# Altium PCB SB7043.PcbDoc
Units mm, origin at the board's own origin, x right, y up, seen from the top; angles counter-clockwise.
Board outline 70 x 43 mm, 2 copper layers (Top Layer, Bottom Layer); 0 components, 0 nets, 4 pads, 0 vias.
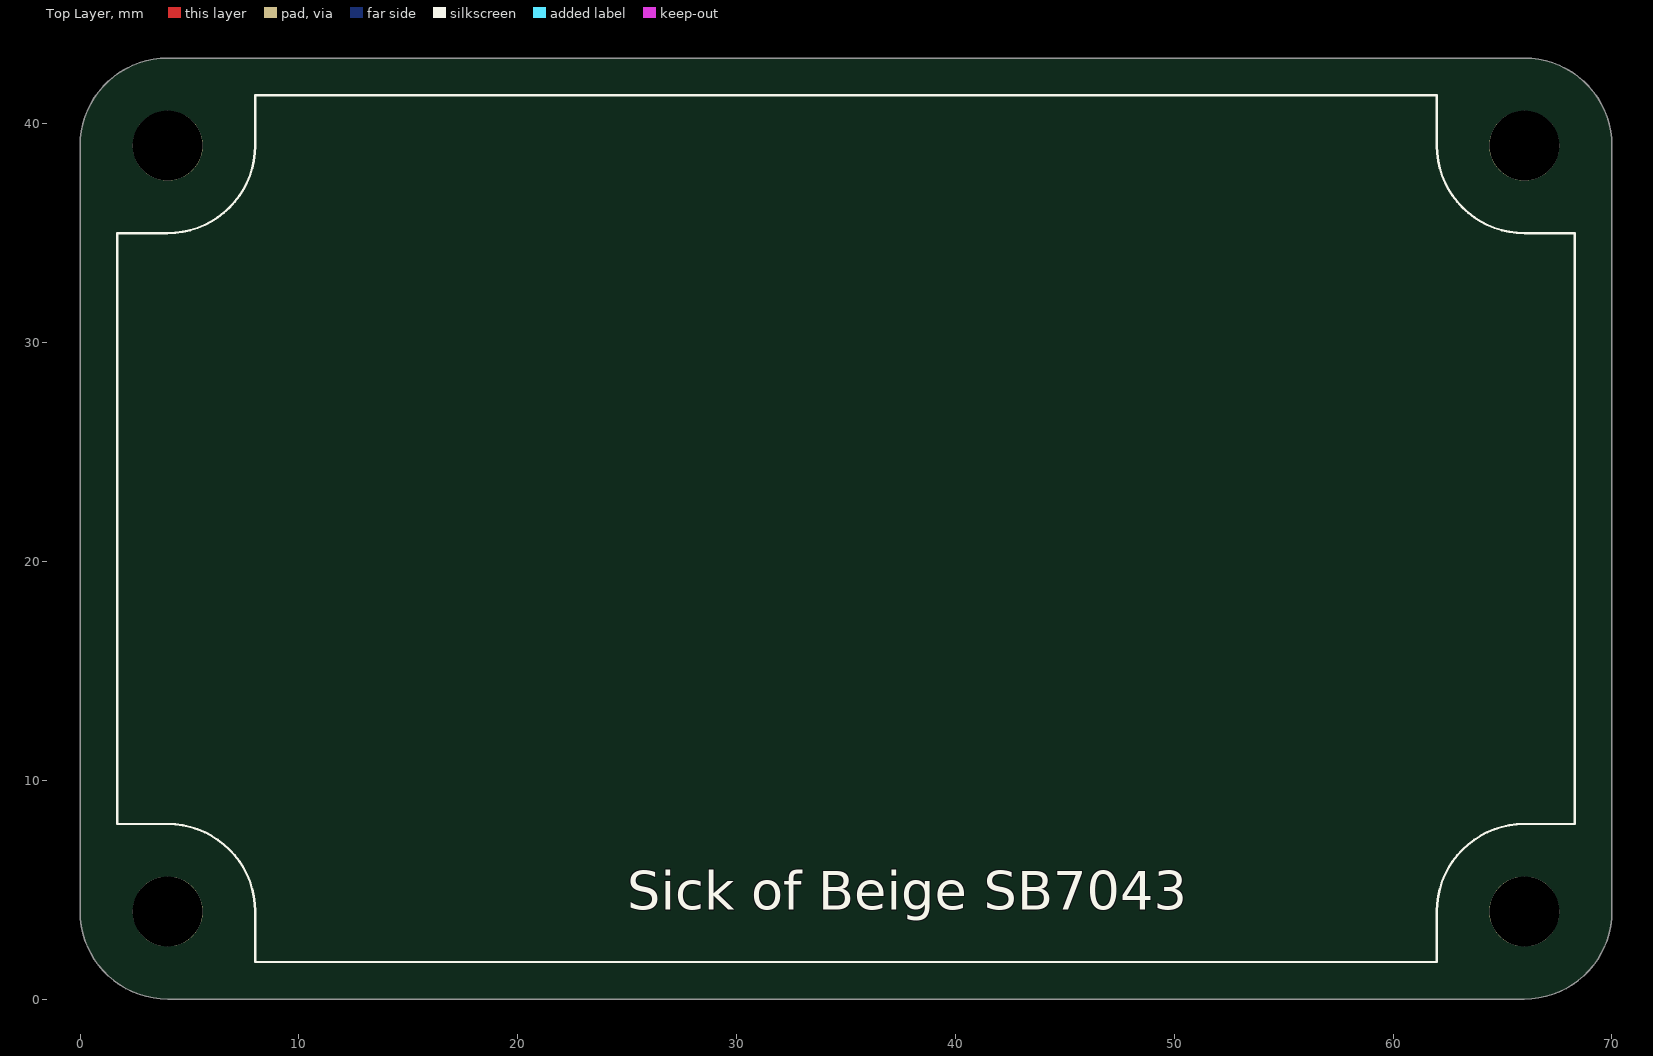
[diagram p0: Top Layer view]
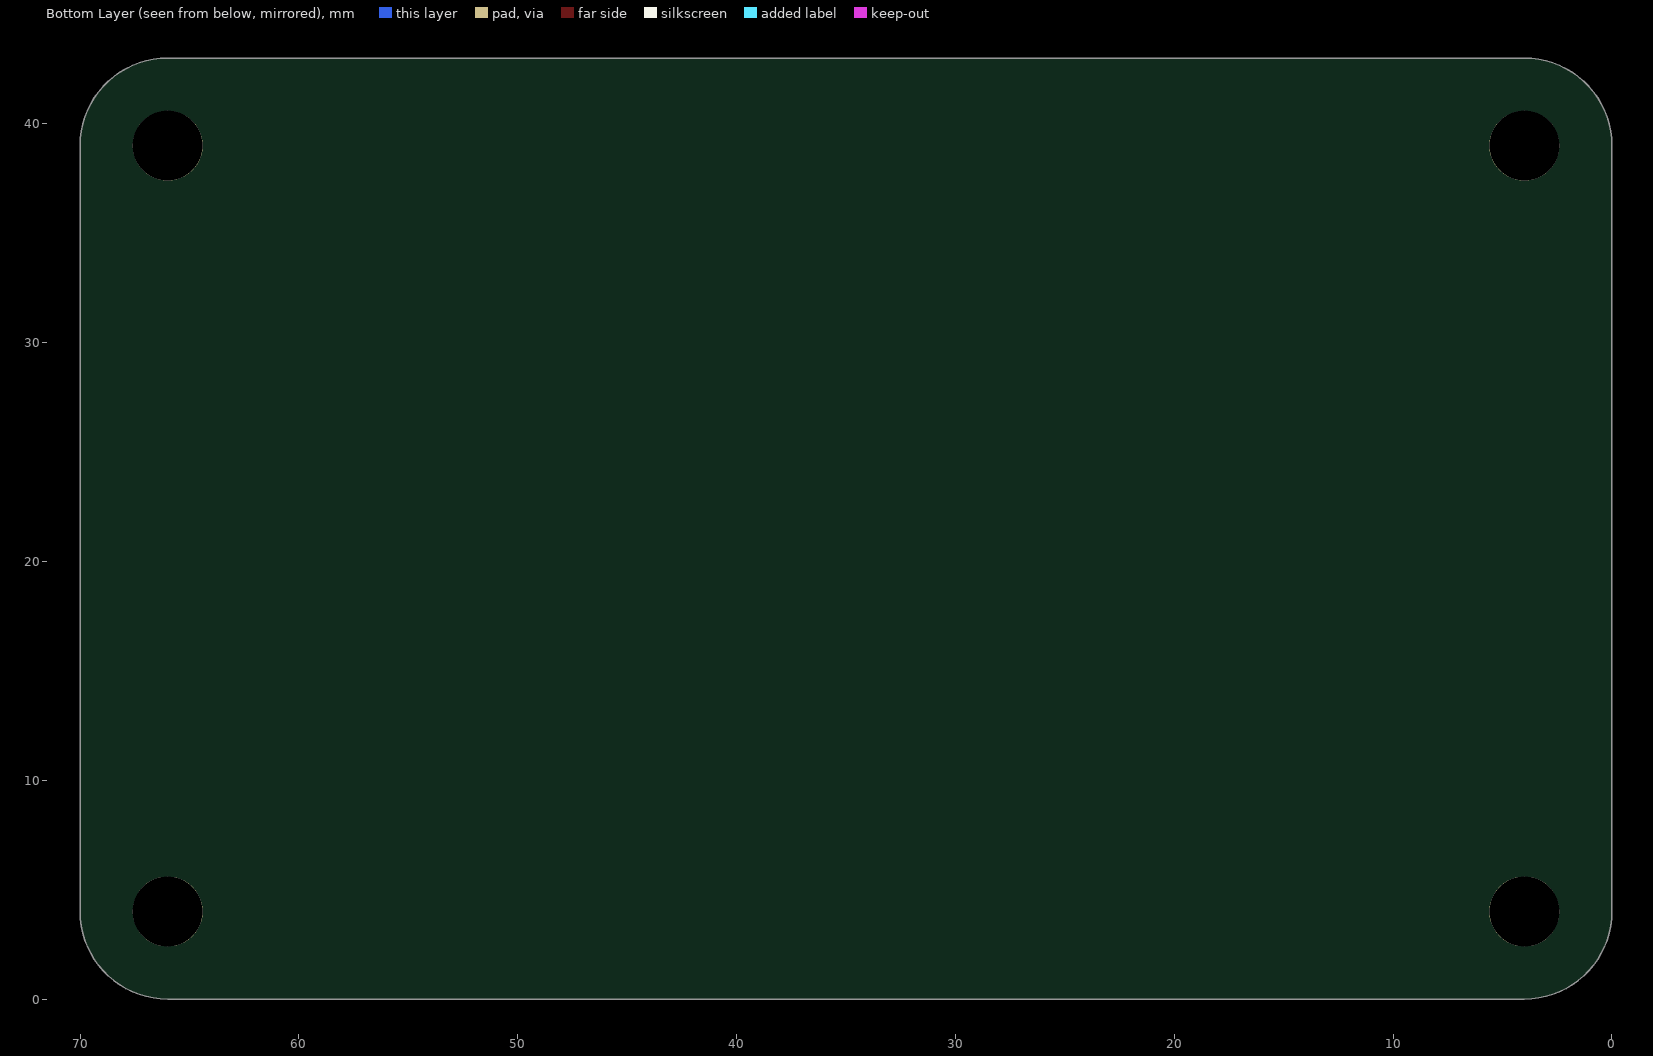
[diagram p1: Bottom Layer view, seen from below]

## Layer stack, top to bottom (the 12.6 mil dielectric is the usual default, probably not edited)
Top Layer: signal copper 0.0356
Dielectric: dielectric 0.32, FR-4, Dk 4.8
Bottom Layer: signal copper 0.0356

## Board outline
4,0 cw(c4,4) 0,4 0,39 cw(c4,39) 4,43 66,43 cw(c66,39) 70,39 70,4 cw(c66,4) 66,0

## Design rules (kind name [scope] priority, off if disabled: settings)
Clearance [All] p1: gap=0.254
PolygonConnect [All] p1: connectstyle=Relief reliefconductorwidth=0.254 reliefentries=4 polygonreliefangle="90 Angle" airgapwidth=0.254
RoutingVias [All] p1: holewidth=0.711 width=1.27 viastyle="Through Hole" minholewidth=0.711 minwidth=1.27 maxholewidth=0.711 maxwidth=1.27
SolderMaskExpansion [All] p1: expansion=0.102
Width [All] p1: maxlimit=0.254 minlimit=0.254 preferedwidth=0.254
28 further rules are at their usual default settings.

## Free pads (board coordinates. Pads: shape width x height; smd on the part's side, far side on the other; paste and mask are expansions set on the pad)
  round 3.2 hole 3.2 unplated: 0(4,4) 1(4,39) 2(66,39) 3(66,4)

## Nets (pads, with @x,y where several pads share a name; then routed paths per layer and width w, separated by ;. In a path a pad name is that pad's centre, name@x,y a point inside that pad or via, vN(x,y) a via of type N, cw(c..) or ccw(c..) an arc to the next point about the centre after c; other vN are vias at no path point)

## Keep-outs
Top Overlay:
  lines w0.102: 1.7,8 4,8 cw(c4,4) 8,4 8,1.7 62,1.7 62,4 cw(c66,4) 66,8 68.3,8 68.3,35 66,35 cw(c66,39) 62,39 62,41.3 8,41.3 8,39 cw(c4,39) 4,35 1.7,35 1.7,8

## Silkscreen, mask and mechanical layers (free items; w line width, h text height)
Top Overlay:
  text "Sick of Beige SB7043" at 25,3.5 h3
Mechanical 1:
  the board outline again, w0.102
Mechanical 4:
  circle w0.102: c66,4 r1.6
  circle w0.102: c4,4 r1.6
  circle w0.102: c4,39 r1.6
  circle w0.102: c66,39 r1.6
  lines w0.102: 0,21.5 70,21.5 ; 35,0 35,43

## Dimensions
66,43 to 66,0 on Mechanical 3
0,4 to 70,4 on Mechanical 3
